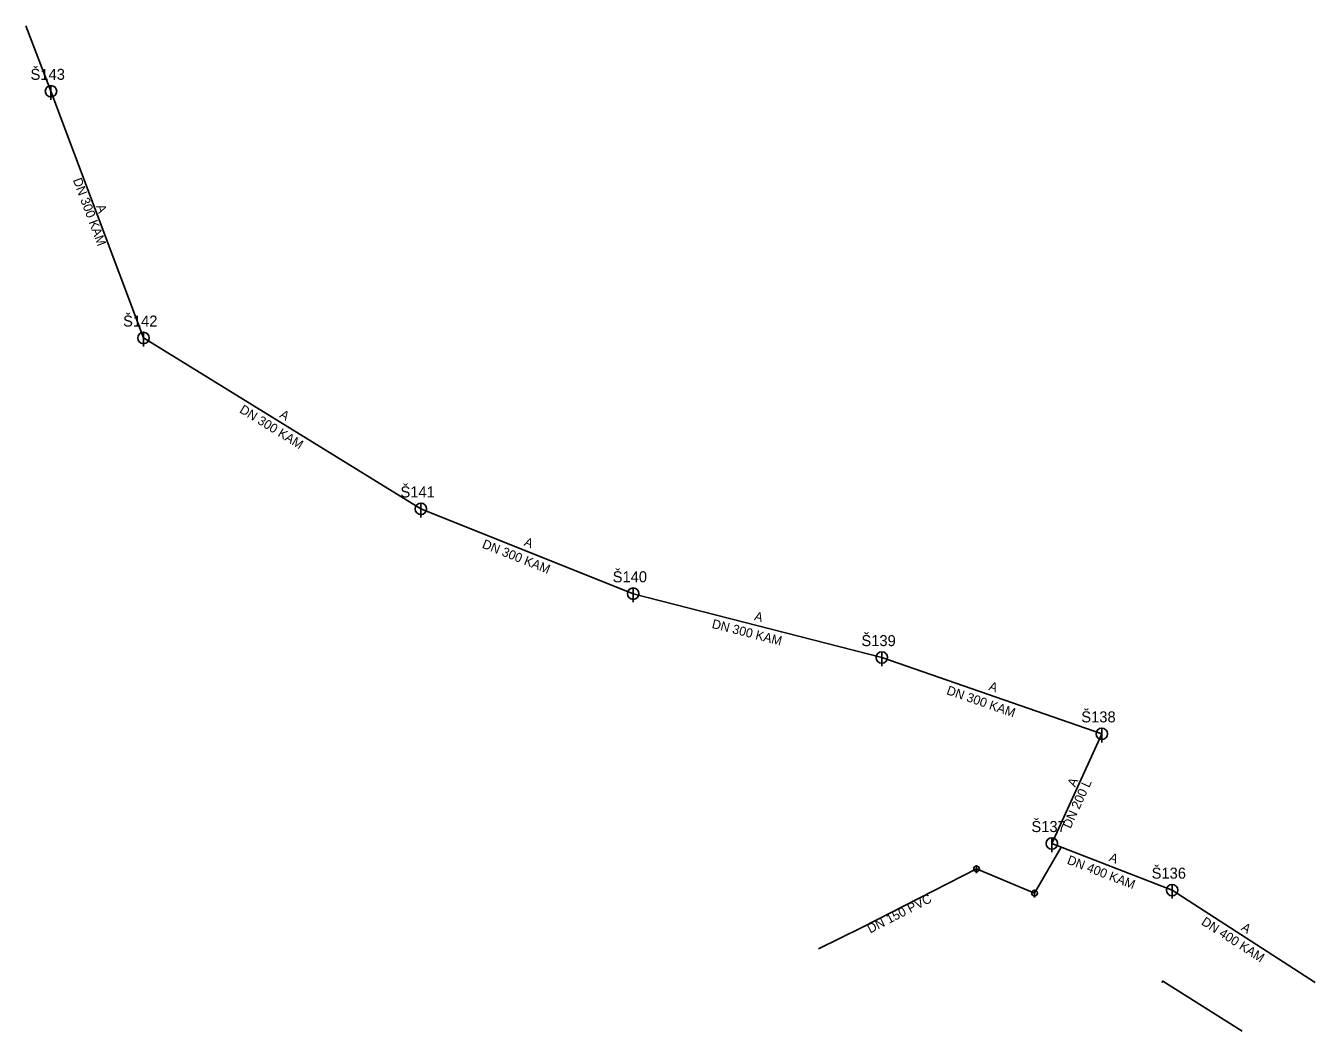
# Model space of a CAD drawing. Extents: x -491345 to -491119, y -1108672 to -1108496.
import ezdxf

# ---------------------------------------------------------------- set-up
doc = ezdxf.new("R2010")
doc.units = 0
for name, color, linetype in [('_pripojka_kanal_destova_priblizne_', 7, 'Continuous'), ('_pripojka_kanal_jednotna_priblizne_', 7, 'Continuous'), ('_stoka_jednotna_smvak_prevzato_z_dokumentace_', 7, 'Continuous'), ('Default', 7, 'Continuous'), ('MoLevel 119', 7, 'Continuous'), ('MoLevel 120', 7, 'Continuous'), ('MoLevel 124', 7, 'Continuous'), ('MoLevel 57', 7, 'Continuous'), ('MoLevel 68', 7, 'Continuous'), ('MoLevel 69', 7, 'Continuous')]:
    doc.layers.add(name, color=color, linetype=linetype)

# ---------------------------------------------------------------- blocks, each defined once
blk = doc.blocks.new('_sachta_kanal_prip_')
at = {"layer": 'Default'}
blk.add_line((0, 0.05), (0, -0.075), dxfattribs=at)
blk.add_circle((0, 0), 0.05, dxfattribs=at)
blk = doc.blocks.new('_sachta_kanal_prevzato_z_dokumentace_')
at = {"layer": 'Default'}
blk.add_line((0, 0.05), (0, -0.075), dxfattribs=at)
blk.add_circle((0, 0), 0.05, dxfattribs=at)

msp = doc.modelspace()

# ---------------------------------------------------------------- linework, layer by layer
at = {"layer": '_pripojka_kanal_destova_priblizne_'}
msp.add_lwpolyline([(-491146.31, -1108663.61), (-491146.12, -1108663.39), (-491132.21, -1108672.17)], dxfattribs=at)
at = {"layer": '_pripojka_kanal_jednotna_priblizne_'}
for p, q in [((-491168.57, -1108647.98), (-491163.89, -1108639.94)), ((-491178.72, -1108643.73), (-491168.57, -1108647.98))]:
    msp.add_line(p, q, dxfattribs=at)
msp.add_lwpolyline([(-491206.39, -1108657.74), (-491198.8, -1108654.01), (-491178.72, -1108643.73)], dxfattribs=at)
at = {"layer": '_stoka_jednotna_smvak_prevzato_z_dokumentace_'}
for p, q in [((-491345.11, -1108496.15), (-491340.7, -1108507.61)), ((-491340.7, -1108507.61), (-491324.5, -1108550.8)), ((-491324.5, -1108550.8), (-491275.96, -1108580.72)), ((-491275.96, -1108580.72), (-491238.82, -1108595.57)), ((-491238.82, -1108595.57), (-491195.29, -1108606.75)), ((-491195.29, -1108606.75), (-491156.81, -1108620.1)), ((-491156.81, -1108620.1), (-491165.54, -1108639.3)), ((-491165.54, -1108639.3), (-491144.5, -1108647.46)), ((-491144.5, -1108647.46), (-491119.45, -1108663.65))]:
    msp.add_line(p, q, dxfattribs=at)

# ---------------------------------------------------------------- block references
at = {"layer": 'MoLevel 119', "xscale": 20, "yscale": 20}
for p in [(-491340.7, -1108507.61), (-491324.5, -1108550.8), (-491275.96, -1108580.72), (-491238.82, -1108595.57), (-491195.29, -1108606.75), (-491156.81, -1108620.1), (-491165.54, -1108639.3), (-491144.5, -1108647.46)]:
    msp.add_blockref('_sachta_kanal_prevzato_z_dokumentace_', p, dxfattribs=at)
at = {"layer": 'MoLevel 57', "xscale": 10, "yscale": 10}
for p in [(-491178.72, -1108643.73), (-491168.57, -1108647.98)]:
    msp.add_blockref('_sachta_kanal_prip_', p, dxfattribs=at)

# ---------------------------------------------------------------- texts
at = {"layer": 'MoLevel 120'}
for s, p in [('Š143', (-491344.28, -1108505.61)), ('Š142', (-491328.08, -1108548.8)), ('Š141', (-491279.54, -1108578.72)), ('Š140', (-491242.4, -1108593.57)), ('Š139', (-491198.87, -1108604.75)), ('Š138', (-491160.39, -1108618.1)), ('Š137', (-491169.12, -1108637.3)), ('Š136', (-491148.08, -1108645.46))]:
    msp.add_text(s, height=1.926, dxfattribs=at).set_placement(p)
at = {"layer": 'MoLevel 124'}
msp.add_text('DN 150 PVC', height=1.605, rotation=27.1079, dxfattribs=at).set_placement((-491197.34, -1108655.07))
at = {"layer": 'MoLevel 68'}
for s, rotation, p in [('DN 300 KAM', 290.5604, (-491336.89, -1108523.13)), ('DN 300 KAM', 328.3504, (-491307.84, -1108563.76)), ('DN 300 KAM', 338.2066, (-491265.37, -1108587.48)), ('DN 300 KAM', 345.5958, (-491225.15, -1108601.54)), ('DN 300 KAM', 340.8666, (-491184.09, -1108613.14)), ('DN 200 L', 65.5493, (-491162.28, -1108636.8)), ('DN 400 KAM', 338.8021, (-491163.01, -1108642.8)), ('DN 400 KAM', 327.1251, (-491139.52, -1108653.39))]:
    msp.add_text(s, height=1.605, rotation=rotation, dxfattribs=at).set_placement(p)
at = {"layer": 'MoLevel 69'}
for rotation, p in [(290.5604, (-491332.84, -1108527.76)), (328.3504, (-491300.82, -1108564.6)), (338.2066, (-491258.03, -1108587.09)), (345.5958, (-491217.72, -1108600.19)), (340.8666, (-491176.7, -1108612.4)), (65.5493, (-491161.46, -1108629.53)), (338.8021, (-491155.66, -1108642.33)), (327.1251, (-491132.55, -1108654.38))]:
    msp.add_text('A', height=1.6, rotation=rotation, dxfattribs=at).set_placement(p)

doc.saveas('drawing.dxf')
